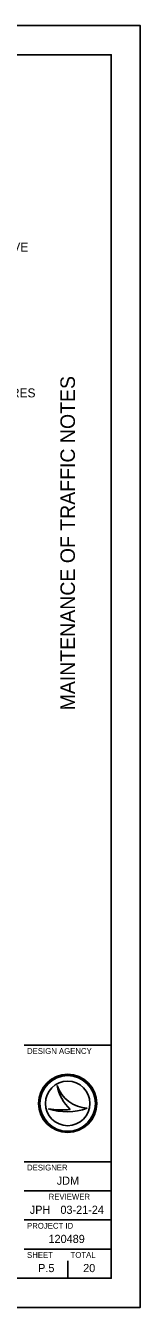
# Model space of a CAD drawing. Extents: x -15.6 to 56.6, y 0 to 56.8.
# Drawn here: x 32.03 to 34, y 0 to 22 of the extents above; entities that cross this region are included whole.
import ezdxf

# ---------------------------------------------------------------- set-up
doc = ezdxf.new("R2010")
doc.units = 0
for name, color, linetype in [('SH_Border', 7, 'Continuous'), ('SH_Cut_Line', 7, 'Continuous'), ('SH_Data', 7, 'Continuous')]:
    doc.layers.add(name, color=color, linetype=linetype)

msp = doc.modelspace()

# ---------------------------------------------------------------- linework, layer by layer
at = {"layer": 'SH_Border'}
for p, q in [((32, 4.5), (33.5, 4.5)), ((32, 2.5), (33.5, 2.5)), ((32, 2), (33.5, 2)), ((32, 1.5), (33.5, 1.5)), ((32, 1), (33.5, 1))]:
    msp.add_line(p, q, dxfattribs=at)
msp.add_lwpolyline([(1.5, 21.5), (33.5, 21.5), (33.5, 0.5), (1.5, 0.5)], close=True, dxfattribs=at)
at = {"layer": 'SH_Cut_Line'}
msp.add_lwpolyline([(0, 0), (34, 0), (34, 22), (0, 22)], close=True, dxfattribs=at)
at = {"layer": 'SH_Data'}
for p, q in [((32.567, 3.81), (32.567, 3.81)), ((32.417, 3.41), (32.417, 3.41)), ((32.75, 3.5), (32.75, 3.5)), ((33.087, 3.419), (33.087, 3.419)), ((32.375, 0.675), (32.375, 0.675)), ((32.75, 0.5), (32.75, 0.8))]:
    msp.add_line(p, q, dxfattribs=at)
for radius in [0.5, 0.477, 0.477, 0.382]:
    msp.add_circle((32.75, 3.5), radius, dxfattribs=at)
for centre, radius, start, end in [((33.116, 3.998), 0.58, 198.9257, 198.9319), ((33.347, 3.97), 0.796, 191.6379, 191.6421), ((33.116, 3.998), 0.58, 198.9319, 267.1657), ((33.347, 3.97), 0.796, 191.6421, 226.0947), ((32.739, 4.37), 1.013, 251.4576, 290.0832), ((32.648, 4.654), 1.266, 259.4964, 259.4995), ((32.739, 4.37), 1.013, 251.4527, 251.4576), ((32.648, 4.654), 1.266, 259.4995, 276.6672)]:
    msp.add_arc(centre, radius, start, end, dxfattribs=at)

# ---------------------------------------------------------------- texts
for s, height, p in [('DISINCENTIVE', 0.154, (30.63, 18.123)), ('SINGLE LANE CLOSURE HOURS SHALL APPLY TO SHORT TERM SHOULDER CLOSURES', 0.154, (23.407, 15.619)), ('DESIGN AGENCY', 0.1, (32.05, 4.35)), ('DESIGNER', 0.1, (32.05, 2.35)), ('JDM', 0.14, (32.562, 2.105)), ('REVIEWER', 0.1, (32.422, 1.85)), ('JPH', 0.14, (32.098, 1.605)), ('03-21-24', 0.14, (32.625, 1.605)), ('PROJECT ID', 0.1, (32.05, 1.35)), ('120489', 0.14, (32.42, 1.105)), ('SHEET', 0.1, (32.05, 0.85)), ('TOTAL', 0.1, (32.8, 0.85)), ('P.5', 0.14, (32.241, 0.605)), ('20', 0.14, (33.017, 0.605))]:
    msp.add_text(s, height=height, dxfattribs=at).set_placement(p)
msp.add_text('MAINTENANCE OF TRAFFIC NOTES', height=0.25, rotation=90, dxfattribs=at).set_placement((32.875, 10.247))

doc.saveas('drawing.dxf')
